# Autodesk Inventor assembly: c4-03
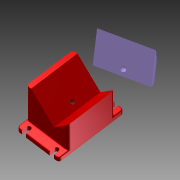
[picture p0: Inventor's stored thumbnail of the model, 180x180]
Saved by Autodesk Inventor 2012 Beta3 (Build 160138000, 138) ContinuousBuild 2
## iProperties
Created: 2010-11
Part Number: c4-03
Document SubType Name: Assembly
Designer: Beta-8540w
Author: Beta-8540w
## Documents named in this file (3)
- C:\Inventor 2012 Essentials\Assemblies\Chapter 4\c4-03.iam
- C:\Inventor 2012 Essentials\Parts\Chapter 4\c4-03.ipt
- C:\Inventor 2012 Essentials\Parts\Chapter 4\c4-04.ipt
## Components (2 placed, 2 different names)
1. c4-03:1
2. c4-04:1
